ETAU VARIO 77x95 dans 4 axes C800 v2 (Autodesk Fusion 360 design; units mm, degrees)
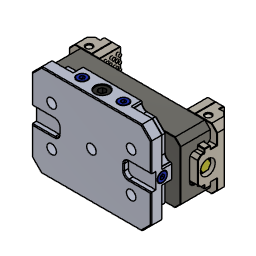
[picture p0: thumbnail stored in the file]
parameter "Ouverture" = 110
base_feature "Base Feature1" OffsetX 0 OffsetY 0 OffsetZ 0
base_feature "Base Feature1"
base_feature "Base Feature1"
position "Position1"
joint_origin "JointOrigin1" OffsetX 0 OffsetY 0 OffsetZ 0
as_built_joint "As-built2"
work_axis "WorkAxis1"
work_point "WorkPoint1"
joint_origin "JointOrigin1" OffsetX 0 OffsetY 0 OffsetZ 0
joint "Assemble3" alignOffsetX 0 alignOffsetY 0 alignOffsetZ 55 (= "Ouverture / 2")
joint "Assemble4" alignOffsetX 0 alignOffsetY 0 alignOffsetZ 55 (= "Ouverture / 2")
ground "Ground1"
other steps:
create_component "CreateComponent1"
create_component "CreateComponent2"
create_component "CreateComponent4"
joint_origin "JointOrigin4" OffsetX 0 OffsetY 0 OffsetZ 0
joint_origin "JointOrigin5" OffsetX 0 OffsetY 0 OffsetZ 0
